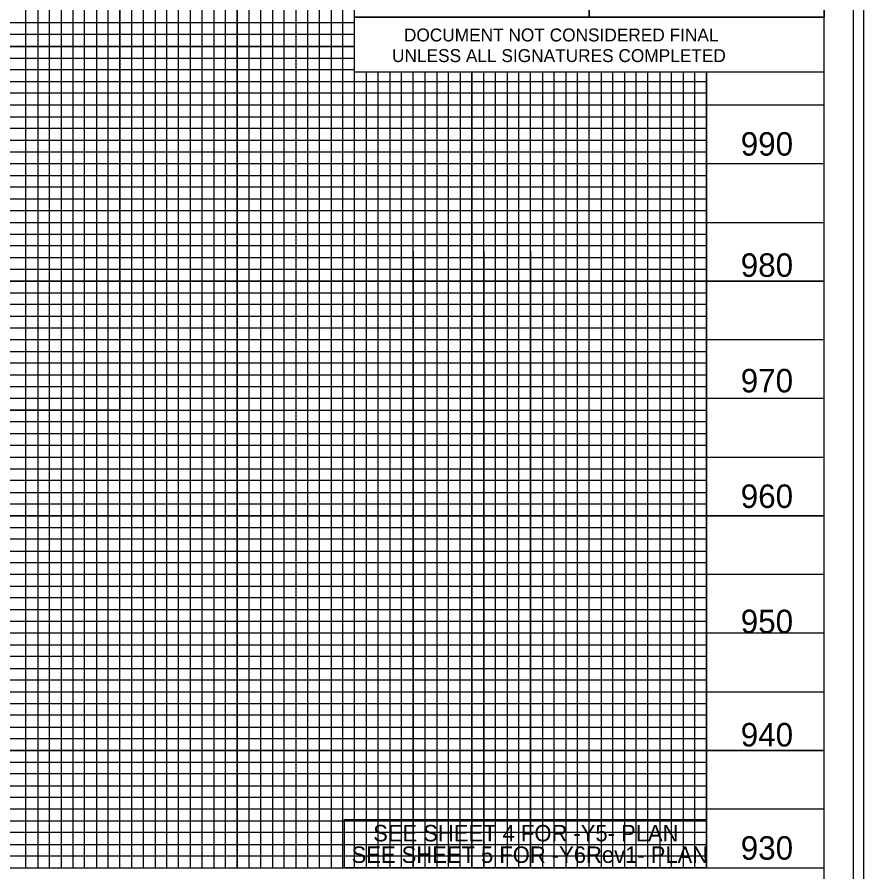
# Model space of a CAD drawing. Extents: x 1621288 to 1629363, y 896995 to 899414.
# Drawn here: x 1628625.6 to 1628986.4, y 897567.9 to 897932.1 of the extents above; entities that cross this region are included whole.
import ezdxf

# ---------------------------------------------------------------- set-up
doc = ezdxf.new("R2010")
doc.units = 0
for name, color, linetype in [('Exist Profile Cell', 7, 'Continuous'), ('Exist Structure Minor Pipes CMAP 112inx75in', 7, 'Continuous'), ('Exist Vertical Profile Ground Line', 7, 'Continuous'), ('Exist Vertical Profile Horizontal Axis Label Major', 7, 'Continuous'), ('Exist XS Ground Line', 7, 'Continuous'), ('Prop Horizontal Alignment', 7, 'Continuous'), ('Prop Horizontal Alignment Curve and Spiral Data', 7, 'Continuous'), ('Prop Vertical Profile Curve Label', 7, 'Continuous'), ('Prop Vertical Profile Grade', 7, 'Continuous'), ('Prop VPI Label', 7, 'Continuous'), ('Sheet Layout Plan Border', 7, 'Continuous'), ('Sheet Layout Profile Border Port 2', 7, 'Continuous')]:
    doc.layers.add(name, color=color, linetype=linetype)

msp = doc.modelspace()

# ---------------------------------------------------------------- linework, layer by layer
at = {"layer": 'Exist Profile Cell'}
for p, q in [((1628769.38, 897929.66), (1627519.38, 897929.66)), ((1628769.38, 897924.66), (1627519.38, 897924.66)), ((1627519.38, 897914.66), (1628769.38, 897914.66)), ((1628769.38, 897909.66), (1627519.38, 897909.66)), ((1627519.38, 897904.66), (1628919.38, 897904.66)), ((1628919.38, 897884.66), (1627519.38, 897884.66)), ((1627519.38, 897879.66), (1628919.38, 897879.66)), ((1628919.38, 897859.66), (1627519.38, 897859.66)), ((1627519.38, 897854.66), (1628919.38, 897854.66)), ((1628919.38, 897834.66), (1627519.38, 897834.66)), ((1627519.38, 897829.66), (1628919.38, 897829.66)), ((1628919.38, 897824.66), (1627519.38, 897824.66)), ((1627519.38, 897814.66), (1628919.38, 897814.66)), ((1628919.38, 897809.66), (1627519.38, 897809.66)), ((1627519.38, 897804.66), (1628919.38, 897804.66)), ((1628919.38, 897799.66), (1627519.38, 897799.66)), ((1627519.38, 897789.66), (1628919.38, 897789.66)), ((1628919.38, 897784.66), (1627519.38, 897784.66)), ((1627519.38, 897779.66), (1628919.38, 897779.66)), ((1628919.38, 897774.66), (1627519.38, 897774.66)), ((1627519.38, 897764.66), (1628919.38, 897764.66)), ((1628919.38, 897759.66), (1627519.38, 897759.66)), ((1627519.38, 897754.66), (1628919.38, 897754.66)), ((1628919.38, 897749.66), (1627519.38, 897749.66)), ((1627519.38, 897739.66), (1628919.38, 897739.66)), ((1628919.38, 897734.66), (1627519.38, 897734.66)), ((1627519.38, 897729.66), (1628919.38, 897729.66)), ((1628919.38, 897724.66), (1627519.38, 897724.66)), ((1627519.38, 897714.66), (1628919.38, 897714.66)), ((1628919.38, 897709.66), (1627519.38, 897709.66)), ((1627519.38, 897704.66), (1628919.38, 897704.66)), ((1628919.38, 897699.66), (1627519.38, 897699.66)), ((1627519.38, 897689.66), (1628919.38, 897689.66)), ((1628919.38, 897684.66), (1627519.38, 897684.66)), ((1628919.38, 897679.66), (1627519.38, 897679.66)), ((1628919.38, 897674.66), (1627519.38, 897674.66)), ((1627519.38, 897664.66), (1628919.38, 897664.66)), ((1628919.38, 897659.66), (1627519.38, 897659.66)), ((1627519.38, 897654.66), (1628919.38, 897654.66)), ((1628919.38, 897649.66), (1627519.38, 897649.66)), ((1627519.38, 897639.66), (1628919.38, 897639.66)), ((1628919.38, 897634.66), (1627519.38, 897634.66)), ((1627519.38, 897629.66), (1628919.38, 897629.66)), ((1628919.38, 897624.66), (1627519.38, 897624.66)), ((1627519.38, 897614.66), (1628919.38, 897614.66)), ((1628919.38, 897609.66), (1627519.38, 897609.66)), ((1627519.38, 897604.66), (1628919.38, 897604.66)), ((1628919.38, 897599.66), (1627519.38, 897599.66)), ((1627519.38, 897589.66), (1628919.38, 897589.66)), ((1628919.38, 897584.66), (1627519.38, 897584.66)), ((1627519.38, 897579.66), (1628919.38, 897579.66))]:
    msp.add_line(p, q, dxfattribs=at)
for points in [[(1628624.38, 897569.66), (1628629.38, 897569.66), (1628629.38, 898069.66), (1628634.38, 898069.66), (1628634.38, 897569.66), (1628639.38, 897569.66), (1628639.38, 898069.66), (1628649.38, 898069.66), (1628649.38, 897569.66), (1628654.38, 897569.66), (1628654.38, 898069.66), (1628659.38, 898069.66), (1628659.38, 897569.66)], [(1628659.38, 897569.66), (1628664.38, 897569.66), (1628664.38, 898069.66)], [(1628674.38, 898069.66), (1628674.38, 897569.66), (1628679.38, 897569.66), (1628679.38, 898069.66)], [(1628684.38, 898069.66), (1628684.38, 897569.66), (1628689.38, 897569.66), (1628689.38, 898069.66)], [(1628699.38, 898069.66), (1628699.38, 897569.66), (1628704.38, 897569.66), (1628704.38, 898069.66)], [(1628709.38, 898069.66), (1628709.38, 897569.66), (1628714.38, 897569.66), (1628714.38, 898069.66)], [(1628724.38, 898069.66), (1628724.38, 897569.66), (1628729.38, 897569.66), (1628729.38, 898069.66)], [(1628734.38, 898069.66), (1628734.38, 897569.66), (1628739.38, 897569.66), (1628739.38, 898069.66)], [(1628749.38, 898069.66), (1628749.38, 897569.66), (1628754.38, 897569.66), (1628754.38, 898069.66)], [(1628759.38, 898069.66), (1628759.38, 897569.66), (1628764.38, 897569.66), (1628764.38, 898069.66)], [(1628774.38, 897908.61), (1628774.38, 897569.66), (1628779.38, 897569.66), (1628779.38, 897908.61)], [(1628784.38, 897908.61), (1628784.38, 897569.66), (1628789.38, 897569.66), (1628789.38, 897908.61)], [(1628799.38, 897908.61), (1628799.38, 897569.66), (1628799.38, 897569.66), (1628804.38, 897569.66), (1628809.38, 897569.66), (1628809.38, 897908.61)], [(1628804.38, 897908.61), (1628804.38, 897569.66)], [(1628814.37, 897908.61), (1628814.28, 897569.71), (1628819.28, 897569.71), (1628824.38, 897569.66), (1628824.38, 897908.61)], [(1628824.38, 897832.46), (1628824.38, 897569.66), (1628829.38, 897569.66), (1628829.38, 897908.61)], [(1628834.38, 897908.61), (1628834.38, 897569.66), (1628839.38, 897569.66), (1628839.38, 897908.61)], [(1628849.38, 897908.61), (1628849.38, 897569.66), (1628854.38, 897569.66), (1628854.38, 897908.61)], [(1628859.38, 897908.61), (1628859.38, 897569.66), (1628864.38, 897569.66), (1628864.38, 897908.61)], [(1628874.38, 897908.61), (1628874.38, 897569.66), (1628879.38, 897569.66), (1628879.38, 897908.61)], [(1628884.38, 897908.61), (1628884.38, 897569.66), (1628889.38, 897569.66), (1628889.38, 897908.61)], [(1628899.38, 897908.61), (1628899.38, 897569.66), (1628904.38, 897569.66), (1628904.38, 897908.61)], [(1628909.38, 897908.61), (1628909.38, 897569.66), (1628914.38, 897569.66), (1628914.38, 897908.61)], [(1628919.38, 897899.66), (1627519.38, 897899.66), (1627519.38, 897889.66), (1628919.38, 897889.66)], [(1628919.38, 897874.66), (1627519.38, 897874.66), (1627519.38, 897864.66), (1628919.38, 897864.66)], [(1628919.38, 897849.66), (1627519.38, 897849.66), (1627519.38, 897839.66), (1628919.38, 897839.66)], [(1628919.38, 897574.66), (1627519.38, 897574.66)]]:
    msp.add_lwpolyline(points, dxfattribs=at)
at = {"layer": 'Exist Structure Minor Pipes CMAP 112inx75in'}
msp.add_lwpolyline([(1628314.38, 898169.66), (1628669.38, 898169.66), (1628669.38, 897764.66), (1628314.38, 897764.66)], close=True, dxfattribs=at)
at = {"layer": 'Exist Vertical Profile Ground Line'}
for p, q in [((1628769.33, 897908.61), (1628769.33, 897932.11)), ((1628769.33, 897932.11), (1628969.37, 897932.11)), ((1628769.33, 897908.61), (1628769.33, 897932.11)), ((1628769.33, 897932.11), (1628969.37, 897932.11)), ((1628969.37, 897932.1), (1628969.37, 897908.6)), ((1628969.37, 897932.1), (1628969.37, 897908.6)), ((1628969.37, 897908.61), (1628769.33, 897908.61)), ((1628969.37, 897908.61), (1628769.33, 897908.61))]:
    msp.add_line(p, q, dxfattribs=at)
at = {"layer": 'Exist Vertical Profile Horizontal Axis Label Major'}
msp.add_lwpolyline([(1628765.14, 897590.3), (1628919.38, 897590.3), (1628919.38, 897569.66), (1628765.14, 897569.66)], close=True, dxfattribs=at)
at = {"layer": 'Exist XS Ground Line'}
msp.add_line((1627469.38, 897569.66), (1628969.38, 897569.66), dxfattribs=at)
for points in [[(1628969.38, 898069.66), (1627469.38, 898069.66), (1627469.38, 897019.66), (1628969.38, 897019.66)], [(1628769.33, 898044.61), (1628869.38, 898044.61), (1628869.38, 897932.11), (1628769.33, 897932.11)], [(1628869.38, 898044.61), (1628969.38, 898044.61), (1628969.38, 897932.11), (1628869.38, 897932.11)]]:
    msp.add_lwpolyline(points, close=True, dxfattribs=at)
at = {"layer": 'Prop Horizontal Alignment'}
msp.add_lwpolyline([(1627519.38, 897908.61), (1627519.38, 897569.66), (1628919.38, 897569.66), (1628919.38, 897908.61)], dxfattribs=at)
at = {"layer": 'Prop Vertical Profile Curve Label'}
msp.add_lwpolyline([(1627315.38, 897017.11), (1628981.88, 897017.11), (1628981.88, 898072.21), (1627315.38, 898072.21)], close=True, dxfattribs=at)
at = {"layer": 'Prop Vertical Profile Grade'}
for points in [[(1628244.38, 897569.66), (1628294.38, 897569.66), (1628294.38, 898069.66), (1628344.38, 898069.66), (1628344.38, 897569.66), (1628394.38, 897569.66), (1628394.38, 898069.66), (1628444.38, 898069.66), (1628444.38, 897569.66), (1628494.38, 897569.66), (1628494.38, 898069.66), (1628544.38, 898069.66), (1628544.38, 897569.66), (1628594.38, 897569.66), (1628594.38, 898069.66), (1628644.38, 898069.66), (1628644.38, 897569.66), (1628694.38, 897569.66), (1628694.38, 898069.66), (1628744.38, 898069.66), (1628744.38, 897569.66), (1628794.38, 897569.66), (1628794.38, 897908.61)], [(1628794.38, 897832.46), (1628794.38, 897569.66), (1628844.38, 897569.66), (1628844.38, 897908.61)], [(1628844.38, 897832.46), (1628844.38, 897569.66), (1628894.38, 897569.66), (1628894.38, 897908.61)], [(1628969.38, 897894.66), (1627469.38, 897894.66), (1627469.38, 897844.66), (1628794.38, 897844.66)], [(1628794.38, 897844.66), (1628969.38, 897844.66)], [(1628969.38, 897794.66), (1627469.38, 897794.66), (1627469.38, 897744.66), (1628969.38, 897744.66)], [(1628969.38, 897694.66), (1627469.38, 897694.66), (1627469.38, 897644.66), (1628969.38, 897644.66)], [(1628969.38, 897594.66), (1627469.38, 897594.66)]]:
    msp.add_lwpolyline(points, dxfattribs=at)
at = {"layer": 'Prop VPI Label'}
for points in [[(1628269.38, 898069.66), (1628319.38, 898069.66), (1628319.38, 897569.66), (1628369.38, 897569.66), (1628369.38, 898069.66), (1628419.38, 898069.66), (1628419.38, 897569.66), (1628469.38, 897569.66), (1628469.38, 898069.66), (1628519.38, 898069.66), (1628519.38, 897569.66), (1628569.38, 897569.66), (1628569.38, 898069.66), (1628619.38, 898069.66), (1628619.38, 897569.66), (1628669.38, 897569.66), (1628669.38, 898069.66), (1628719.38, 898069.66), (1628719.38, 897569.66), (1628769.38, 897569.66), (1628769.38, 898069.66), (1628795.68, 898069.66)], [(1628769.38, 897969.66), (1627469.38, 897969.66), (1627469.38, 897919.66), (1628769.38, 897919.66)], [(1628919.38, 897908.61), (1628919.38, 897569.66), (1628969.38, 897569.66), (1628969.38, 897919.66)], [(1628819.38, 897908.61), (1628819.38, 897569.66), (1628869.38, 897569.66), (1628869.38, 897569.66), (1628869.38, 897908.61)], [(1628969.38, 897869.66), (1627469.38, 897869.66), (1627469.38, 897819.66), (1628969.38, 897819.66)], [(1628969.38, 897769.66), (1627469.38, 897769.66), (1627469.38, 897719.66), (1628969.38, 897719.66)], [(1628969.38, 897669.66), (1627469.38, 897669.66), (1627469.38, 897669.66), (1627469.38, 897619.66), (1628969.38, 897619.66)]]:
    msp.add_lwpolyline(points, dxfattribs=at)
at = {"layer": 'Sheet Layout Plan Border'}
msp.add_lwpolyline([(1627302.38, 896994.66), (1628986.38, 896994.66), (1628986.38, 898094.66), (1627302.38, 898094.66)], close=True, dxfattribs=at)
at = {"layer": 'Sheet Layout Profile Border Port 2'}
for p, q in [((1628669.38, 897569.66), (1628669.38, 898069.66)), ((1628719.38, 897569.66), (1628719.38, 898069.66)), ((1628769.38, 897569.66), (1628769.38, 897932.11)), ((1628769.38, 897919.66), (1627469.38, 897919.66)), ((1628819.38, 897569.66), (1628819.38, 897908.61)), ((1628869.38, 897569.66), (1628869.38, 897908.61)), ((1628919.38, 897569.66), (1628919.38, 897908.61)), ((1628969.38, 897869.66), (1627469.38, 897869.66)), ((1628969.38, 897819.66), (1627469.38, 897819.66)), ((1628969.38, 897769.66), (1627469.38, 897769.66)), ((1628969.38, 897719.66), (1627469.38, 897719.66)), ((1628969.38, 897669.66), (1627469.38, 897669.66)), ((1628969.38, 897619.66), (1627469.38, 897619.66))]:
    msp.add_line(p, q, dxfattribs=at)

# ---------------------------------------------------------------- texts
at = {"layer": 'Exist Vertical Profile Ground Line'}
for s, p in [('DOCUMENT NOT CONSIDERED FINAL', (1628790.4, 897921.77)), ('DOCUMENT NOT CONSIDERED FINAL', (1628790.4, 897921.77)), ('UNLESS ALL SIGNATURES COMPLETED', (1628785.33, 897912.97)), ('UNLESS ALL SIGNATURES COMPLETED', (1628785.33, 897912.97))]:
    msp.add_text(s, height=5.5, dxfattribs=at).set_placement(p)
at = {"layer": 'Exist Vertical Profile Horizontal Axis Label Major'}
for s, p in [('SEE SHEET 4 FOR -Y5- PLAN', (1628777.32, 897580.95)), ('SEE SHEET 5 FOR -Y6Rev1- PLAN', (1628768.11, 897571.77))]:
    msp.add_text(s, height=7, dxfattribs=at).set_placement(p)
at = {"layer": 'Prop Horizontal Alignment Curve and Spiral Data'}
for s, p in [('990', (1628933.9, 897873.11)), ('980', (1628933.9, 897821.47)), ('970', (1628933.9, 897772.24)), ('960', (1628933.9, 897723.01)), ('950', (1628933.9, 897669.66)), ('940', (1628933.9, 897621.39)), ('930', (1628933.9, 897573.14))]:
    msp.add_text(s, height=10, dxfattribs=at).set_placement(p)

doc.saveas('drawing.dxf')
